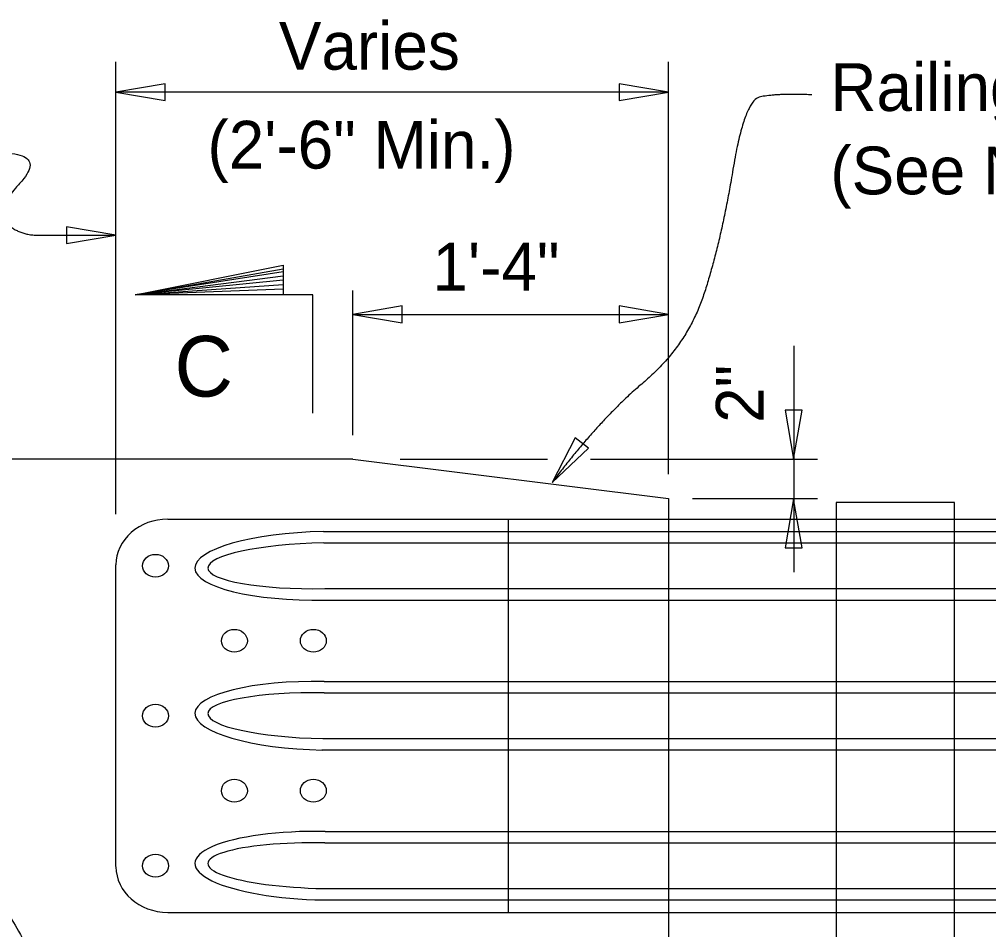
# Model space of a CAD drawing. Extents: x 1.5 to 68.7, y 0 to 31.
# Drawn here: x 28.879 to 32.972, y 12.779 to 16.622 of the extents above; entities that cross this region are included whole.
import ezdxf

# ---------------------------------------------------------------- set-up
doc = ezdxf.new("R2010")
doc.units = 0
for name, color, linetype in [('Dimension', 7, 'Continuous'), ('Miscellaneous', 7, 'Continuous'), ('TextStructures', 7, 'Continuous'), ('TrafBarrierConc', 7, 'Continuous')]:
    doc.layers.add(name, color=color, linetype=linetype)

# ---------------------------------------------------------------- blocks, each defined once
blk = doc.blocks.new('Terminator-Arrow')
at = {"layer": 'Dimension'}
blk.add_lwpolyline([(0, 0), (-0.0004099, 0.0000694), (-0.0004099, -0.0000694)], close=True, dxfattribs=at)

msp = doc.modelspace()

# ---------------------------------------------------------------- linework, layer by layer
at = {"layer": 'Dimension'}
for p, q in [((29.2871, 14.5331), (29.2871, 16.4428)), ((31.6205, 14.7016), (31.6205, 16.4428)), ((31.6205, 16.3147), (29.2871, 16.3147)), ((29.3681, 15.4594), (29.9931, 15.5694)), ((29.9931, 15.5561), (29.3681, 15.4594)), ((29.3681, 15.4594), (29.9931, 15.5394)), ((29.9931, 15.5211), (29.3681, 15.4594)), ((29.3681, 15.4594), (29.9931, 15.5027)), ((29.9931, 15.4827), (29.3681, 15.4594)), ((30.2872, 14.8661), (30.2872, 15.4777)), ((30.2872, 15.3768), (31.6205, 15.3768)), ((32.1489, 15.2437), (32.1489, 14.2876)), ((30.4865, 14.7653), (31.1092, 14.7653)), ((31.2909, 14.7653), (32.2497, 14.7653)), ((31.7213, 14.5986), (32.2497, 14.5986))]:
    msp.add_line(p, q, dxfattribs=at)
for points in [[(29.2871, 16.3147), (29.4954, 16.2794), (29.4954, 16.3499)], [(31.6205, 16.3147), (31.4123, 16.3499), (31.4123, 16.2794)], [(29.2871, 15.7107), (29.0789, 15.7459), (29.0789, 15.6754)], [(30.2872, 15.3769), (30.4955, 15.3416), (30.4955, 15.4121)], [(31.6205, 15.3769), (31.4123, 15.4121), (31.4123, 15.3416)], [(31.1287, 14.6675), (31.2824, 14.8124), (31.2261, 14.855)]]:
    msp.add_lwpolyline(points, close=True, dxfattribs=at)
msp.add_lwpolyline([(30.1181, 14.9594), (30.1181, 15.4594), (29.3681, 15.4594), (29.9931, 15.5844), (29.9931, 15.4594)], dxfattribs=at)
for points in [[(32.2251, 16.3037), (32.0694, 16.3102), (31.9396, 16.2777), (31.8423, 15.6869), (31.6996, 15.2453), (31.3298, 14.9337), (31.1287, 14.6675)], [(28.3524, 16.0586), (28.5909, 16.0586), (28.997, 16.0586), (28.7722, 15.8101), (28.879, 15.7106), (29.0455, 15.7106), (29.2872, 15.7106)], [(28.4708, 12.9203), (28.7034, 12.864), (28.7449, 13.0099), (29.089, 12.3912), (29.2714, 12.2154)]]:
    msp.add_open_spline(points, degree=2, dxfattribs=at)
at = {"layer": 'Miscellaneous'}
for p, q in [((29.5056, 14.512), (36.5106, 14.512)), ((30.9451, 12.852), (30.9451, 14.5121)), ((30.1632, 14.4598), (36.5106, 14.4598)), ((30.1645, 14.4116), (36.5106, 14.4116)), ((29.2871, 13.0448), (29.2871, 14.3193)), ((30.1692, 14.2188), (36.5106, 14.2188)), ((30.1703, 14.1705), (36.5106, 14.1705)), ((30.1669, 13.8266), (36.5106, 13.8266)), ((30.1656, 13.7783), (36.5106, 13.7783)), ((30.1604, 13.5855), (36.5106, 13.5855)), ((30.1563, 13.5374), (36.5106, 13.5374)), ((30.1703, 13.1934), (36.5106, 13.1934)), ((30.1692, 13.1452), (36.5106, 13.1452)), ((30.1629, 12.9524), (36.5106, 12.9524)), ((30.164, 12.9042), (36.5106, 12.9042)), ((29.5056, 12.8519), (36.5106, 12.8519))]:
    msp.add_line(p, q, dxfattribs=at)
msp.add_lwpolyline([(32.8274, 10.853), (32.8274, 14.5819), (32.3274, 14.5819), (32.3274, 10.853)], dxfattribs=at)
for centre, major_axis, ratio, start_param, end_param in [((29.5058, 14.3192), (0.2185, 0), 0.882613, 1.570796, 3.141593), ((30.1669, 14.3152), (-0.5464, -0.0102), 0.264749, 4.713933, 7.855525), ((30.1669, 14.3152), (-0.4917, -0.0093), 0.196063, 4.713495, 7.855087), ((30.1633, 13.6819), (-0.5428, 0.0103), 0.266477, 4.71081, 7.852402), ((30.1633, 13.6819), (-0.4882, 0.0094), 0.197486, 4.711258, 7.85285), ((30.1669, 13.0488), (-0.5464, 0.0102), 0.264749, 4.710845, 7.852438), ((30.1669, 13.0488), (-0.4917, 0.0093), 0.196063, 4.711283, 7.852876), ((29.5058, 13.0447), (0.2185, 0), 0.882613, 3.141593, 4.712389)]:
    msp.add_ellipse(centre, major_axis=major_axis, ratio=ratio, start_param=start_param, end_param=end_param, dxfattribs=at)
for centre in [(29.4539, 14.3152), (29.7872, 13.9985), (30.1206, 13.9986), (29.4539, 13.682), (29.7872, 13.3655), (30.1206, 13.3654), (29.4539, 13.0488)]:
    msp.add_ellipse(centre, major_axis=(0.0547, 0), ratio=0.882613, dxfattribs=at)
at = {"layer": 'TrafBarrierConc'}
for p, q in [((30.2872, 14.7653), (25.4726, 14.7653)), ((30.2872, 14.7653), (31.6205, 14.5986)), ((31.6205, 14.5986), (31.6205, 11.932))]:
    msp.add_line(p, q, dxfattribs=at)

# ---------------------------------------------------------------- block references
at = {"layer": 'Dimension', "xscale": 506.349, "yscale": 512.1577380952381}
for p, rotation in [((32.1485, 14.765), -90), ((32.1485, 14.5983), 90)]:
    msp.add_blockref('Terminator-Arrow', p, dxfattribs=dict(at, rotation=rotation))

# ---------------------------------------------------------------- texts
at = {"layer": 'Dimension'}
for s, p in [('Railing End Transition ', (32.3035, 16.2355)), ('(See Note 2)', (32.3035, 15.8835))]:
    msp.add_text(s, height=0.2016, dxfattribs=at).set_placement(p)
at = {"layer": 'TextStructures'}
for s, height, p in [('Varies', 0.2016, (29.975, 16.4099)), ('(2\'-6" Min.)', 0.2016, (29.6735, 15.9923)), ('1\'-4"', 0.2016, (30.6234, 15.4773)), ('C', 0.256, (29.5343, 15.0297))]:
    msp.add_text(s, height=height, dxfattribs=at).set_placement(p)
msp.add_text('2"', height=0.2016, rotation=90, dxfattribs=at).set_placement((32.0217, 14.9185))

doc.saveas('drawing.dxf')
